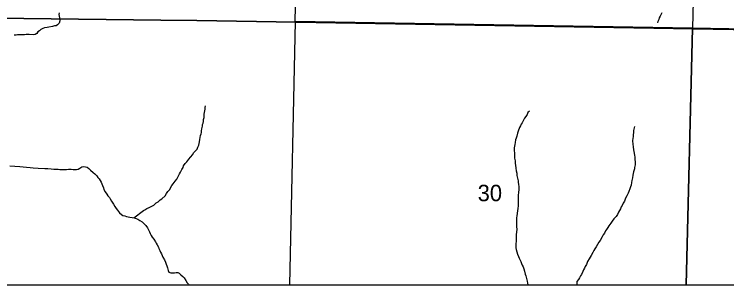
# Model space of a CAD drawing. Extents: x -10 to 158, y 8 to 33.
# Drawn here: x 41.577 to 43.396, y 15.155 to 15.845 of the extents above; entities that cross this region are included whole.
import ezdxf

# ---------------------------------------------------------------- set-up
doc = ezdxf.new("R2010")
doc.units = 0
for name, color, linetype in [('GM_X_Corporation', 7, 'Continuous'), ('GM_X_Minor_River', 7, 'Continuous'), ('GM_X_Section_Text', 7, 'Continuous')]:
    doc.layers.add(name, color=color, linetype=linetype)

msp = doc.modelspace()

# ---------------------------------------------------------------- linework, layer by layer
at = {"layer": 'GM_X_Corporation'}
for points in [[(41.4462, 15.1552), (44.324, 15.1552), (44.324, 21.9552), (41.5663, 21.9552), (41.564, 21.7852), (41.5618, 21.6932), (41.5485, 21.0008), (41.5233, 19.7709), (41.5184, 19.3523), (41.5125, 19.0268), (41.5025, 18.3092), (41.4916, 17.5539), (41.4842, 16.8508), (41.4581, 15.8355), (41.458, 15.832), (41.4573, 15.7877), (41.4556, 15.685), (41.4591, 15.5415), (41.4568, 15.5324), (41.4547, 15.4323)], [(44.324, 15.79), (44.324, 21.73), (42.4015, 21.7711), (42.3578, 21.7721), (41.564, 21.7852), (41.5618, 21.6932), (41.5485, 21.0008), (41.5233, 19.7709), (41.5184, 19.3523), (41.5125, 19.0268), (41.5025, 18.3092), (41.4916, 17.5539), (41.4842, 16.8508), (41.4581, 15.8355), (41.4922, 15.8348), (41.6019, 15.8337), (41.9512, 15.8301), (42.0434, 15.8291), (43.9186, 15.7973)], [(43.3329, 16.8264), (43.3079, 15.8092), (42.2946, 15.8263), (42.3174, 16.8404)], [(44.324, 15.791), (44.324, 16.8057), (43.3329, 16.8264), (43.3079, 15.8092)], [(41.4462, 15.1552), (44.324, 15.1552), (44.324, 15.79), (43.9186, 15.7973), (42.0434, 15.8291), (41.9512, 15.8301), (41.6019, 15.8337), (41.4922, 15.8348), (41.4581, 15.8355), (41.458, 15.832), (41.4573, 15.7877), (41.4556, 15.685), (41.4591, 15.5415), (41.4568, 15.5324), (41.4547, 15.4323)], [(42.2795, 15.1552), (43.2924, 15.1552), (43.3079, 15.8092), (42.2946, 15.8263)], [(44.324, 15.3668), (44.324, 15.791), (43.3079, 15.8092), (43.2924, 15.1552), (44.3189, 15.1552)]]:
    msp.add_lwpolyline(points, close=True, dxfattribs=at)
at = {"layer": 'GM_X_Minor_River'}
for points in [[(41.6917, 15.8489), (41.6907, 15.8444), (41.6915, 15.8398), (41.6931, 15.8361), (41.6935, 15.8319), (41.6936, 15.8281), (41.6922, 15.8224), (41.6877, 15.8182), (41.684, 15.8158), (41.6798, 15.815), (41.6753, 15.8138), (41.6655, 15.8121), (41.6617, 15.8112), (41.6549, 15.81), (41.65, 15.8084), (41.6452, 15.806), (41.6414, 15.8029), (41.6377, 15.8002), (41.6347, 15.7956), (41.6303, 15.7929), (41.6265, 15.7928), (41.6155, 15.7934), (41.6075, 15.7932), (41.6038, 15.7928), (41.5988, 15.7927), (41.5943, 15.7922), (41.5901, 15.7925), (41.586, 15.7925), (41.5822, 15.792), (41.5773, 15.7919)], [(43.23, 15.8483), (43.2278, 15.8437), (43.2256, 15.8399), (43.2234, 15.8357), (43.2219, 15.8318), (43.2198, 15.8265), (43.2187, 15.8227)], [(41.8827, 15.3256), (41.9072, 15.3444), (41.9109, 15.3464), (41.9154, 15.3499), (41.9218, 15.3523), (41.9271, 15.3546), (41.9334, 15.3585), (41.9398, 15.364), (41.945, 15.3667), (41.9498, 15.3717), (41.9539, 15.3745), (41.9621, 15.3822), (41.9658, 15.3879), (41.9691, 15.3926), (41.974, 15.398), (41.9758, 15.4022), (41.9798, 15.4083), (41.9832, 15.4122), (41.988, 15.4194), (41.992, 15.4245), (41.995, 15.4291), (41.9964, 15.4329), (41.9994, 15.4382), (42.0019, 15.4421), (42.0052, 15.449), (42.0086, 15.454), (42.0096, 15.4585), (42.0133, 15.4647), (42.0178, 15.4685), (42.0229, 15.4754), (42.027, 15.4808), (42.0329, 15.487), (42.0351, 15.4912), (42.0392, 15.4962), (42.0437, 15.5012), (42.0462, 15.5058), (42.048, 15.5108), (42.0491, 15.515), (42.0498, 15.5199), (42.0512, 15.5256), (42.0529, 15.5359), (42.0543, 15.5397), (42.055, 15.5435), (42.0553, 15.5473), (42.0564, 15.5527), (42.0574, 15.5595), (42.0581, 15.5637), (42.0592, 15.5675), (42.0602, 15.5717), (42.0605, 15.5763), (42.0616, 15.5816), (42.0619, 15.5854), (42.0622, 15.5903), (42.0635, 15.5987), (42.0642, 15.6025), (42.0645, 15.6074), (42.0652, 15.6112)], [(42.8923, 15.5981), (42.8882, 15.5942), (42.886, 15.5896), (42.8827, 15.5846), (42.8797, 15.5796), (42.876, 15.5735), (42.8731, 15.5681), (42.8709, 15.5643), (42.8691, 15.5601), (42.8669, 15.5559), (42.8633, 15.5467), (42.8615, 15.5414), (42.8601, 15.5342), (42.8579, 15.5292), (42.8568, 15.525), (42.8558, 15.5181), (42.8544, 15.5124), (42.8537, 15.5086), (42.8534, 15.5041), (42.8527, 15.4999), (42.8537, 15.4881), (42.8538, 15.484), (42.8543, 15.4783), (42.8555, 15.4715), (42.856, 15.4647), (42.8568, 15.4605), (42.8577, 15.4522), (42.8586, 15.4454), (42.8595, 15.4397), (42.8603, 15.4336), (42.8616, 15.4272), (42.8632, 15.4204), (42.8633, 15.4166), (42.8641, 15.4109), (42.8646, 15.406), (42.8647, 15.3992), (42.8641, 15.3893), (42.8635, 15.3844), (42.8629, 15.3741), (42.863, 15.3692), (42.8631, 15.3646), (42.8632, 15.3563), (42.8622, 15.3498), (42.8616, 15.3434), (42.8599, 15.3312), (42.8592, 15.3259), (42.8589, 15.3206), (42.8587, 15.3145), (42.8587, 15.3103), (42.8592, 15.3031), (42.8597, 15.2967), (42.8585, 15.2826), (42.8585, 15.2788), (42.8582, 15.2746), (42.8583, 15.2705), (42.858, 15.2652), (42.8577, 15.2606), (42.8575, 15.2534), (42.8575, 15.2496), (42.858, 15.2447), (42.8612, 15.2333), (42.864, 15.2269), (42.8656, 15.2232), (42.8703, 15.2142), (42.8722, 15.2096), (42.8738, 15.2055), (42.8762, 15.2006), (42.8774, 15.1957), (42.8794, 15.1897), (42.8814, 15.1821), (42.8826, 15.1779), (42.8843, 15.1715), (42.8859, 15.1643), (42.8875, 15.1591), (42.8881, 15.1552)], [(43.1601, 15.5588), (43.1591, 15.555), (43.158, 15.5485), (43.1578, 15.5424), (43.1571, 15.5386), (43.1564, 15.5326), (43.1561, 15.5288), (43.1555, 15.5219), (43.1556, 15.514), (43.1565, 15.5068), (43.1578, 15.4988), (43.1586, 15.495), (43.1599, 15.4856), (43.1607, 15.4803), (43.1612, 15.4735), (43.1617, 15.4697), (43.1618, 15.4648), (43.1615, 15.461), (43.1604, 15.4545), (43.1601, 15.4507), (43.158, 15.4427), (43.1569, 15.4389), (43.1559, 15.4347), (43.1548, 15.4282), (43.1538, 15.4214), (43.1528, 15.416), (43.1514, 15.4092), (43.1503, 15.4046), (43.1485, 15.3996), (43.146, 15.3932), (43.1438, 15.3886), (43.1409, 15.3817), (43.1376, 15.3759), (43.1343, 15.3683), (43.131, 15.3633), (43.1285, 15.3576), (43.1259, 15.3537), (43.1241, 15.3491), (43.1193, 15.34), (43.1164, 15.3346), (43.1131, 15.3292), (43.1075, 15.323), (43.1031, 15.3177), (43.1001, 15.3123), (43.0949, 15.3058), (43.092, 15.3015), (43.0891, 15.2962), (43.0865, 15.2923), (43.0839, 15.287), (43.0806, 15.2824), (43.078, 15.2774), (43.0725, 15.2682), (43.0692, 15.2636), (43.0655, 15.2574), (43.0626, 15.2521), (43.0593, 15.2467), (43.0563, 15.2421), (43.0538, 15.2375), (43.0494, 15.2298), (43.0472, 15.2256), (43.0446, 15.221), (43.0405, 15.2145), (43.0376, 15.2072), (43.0343, 15.2019), (43.0329, 15.1977), (43.0303, 15.1931), (43.0285, 15.1889), (43.0248, 15.1816), (43.0226, 15.1778), (43.0197, 15.1732), (43.0171, 15.1682), (43.0134, 15.1636), (43.0128, 15.1594), (43.0128, 15.1552)], [(41.5657, 15.4583), (41.5919, 15.4565), (41.5998, 15.4559), (41.6085, 15.4553), (41.6176, 15.4543), (41.6252, 15.4537), (41.6385, 15.4528), (41.6552, 15.4516), (41.6631, 15.4513), (41.6711, 15.4507), (41.6779, 15.4501), (41.6847, 15.4498), (41.6893, 15.4495), (41.6938, 15.4492), (41.6976, 15.4489), (41.7104, 15.4491), (41.7161, 15.4496), (41.7222, 15.4497), (41.7278, 15.4494), (41.7324, 15.4491), (41.7362, 15.4492), (41.7403, 15.45), (41.7448, 15.4527), (41.7497, 15.4555), (41.755, 15.4563), (41.7588, 15.456), (41.763, 15.4546), (41.7675, 15.4516), (41.7718, 15.4475), (41.7787, 15.4412), (41.7829, 15.4379), (41.7879, 15.433), (41.791, 15.4289), (41.7941, 15.4252), (41.7965, 15.4206), (41.7992, 15.4169), (41.8008, 15.4124), (41.8024, 15.4086), (41.8051, 15.4026), (41.8063, 15.3984), (41.8095, 15.3917), (41.8133, 15.3864), (41.8165, 15.3819), (41.8203, 15.3778), (41.8223, 15.3741), (41.8258, 15.368), (41.8308, 15.3609), (41.8343, 15.3549), (41.8371, 15.35), (41.8406, 15.3452), (41.8463, 15.3388), (41.851, 15.334), (41.8548, 15.3321), (41.8597, 15.3307), (41.8639, 15.3289), (41.8677, 15.3282), (41.8719, 15.3271), (41.878, 15.3265), (41.8837, 15.3254), (41.8882, 15.3244), (41.8924, 15.3225), (41.8982, 15.3192), (41.9035, 15.3152), (41.9074, 15.3118), (41.9128, 15.3066), (41.9174, 15.3006), (41.919, 15.2965), (41.9225, 15.2897), (41.9245, 15.2855), (41.9268, 15.281), (41.9296, 15.2769), (41.9338, 15.2713), (41.9377, 15.2649), (41.9397, 15.2608), (41.942, 15.257), (41.9451, 15.2514), (41.9463, 15.2476), (41.9487, 15.2427), (41.9507, 15.2382), (41.953, 15.2337), (41.955, 15.2295), (41.9566, 15.2258), (41.9605, 15.2186), (41.9629, 15.2126), (41.9648, 15.2077), (41.9664, 15.2036), (41.968, 15.1983)], [(41.968, 15.1983), (41.9701, 15.1911), (41.972, 15.187), (41.9766, 15.1852), (41.9815, 15.1852), (41.986, 15.1857), (41.9902, 15.1865), (41.9944, 15.1862), (41.9982, 15.1844), (42.0028, 15.1807), (42.0074, 15.1766), (42.0109, 15.1725), (42.0155, 15.1657), (42.0183, 15.1601), (42.0218, 15.1563), (42.0232, 15.1552)]]:
    msp.add_lwpolyline(points, dxfattribs=at)

# ---------------------------------------------------------------- texts
at = {"layer": 'GM_X_Section_Text'}
msp.add_text('30', height=0.04186, rotation=0, dxfattribs=at).set_placement((42.7599, 15.3682))

doc.saveas('drawing.dxf')
